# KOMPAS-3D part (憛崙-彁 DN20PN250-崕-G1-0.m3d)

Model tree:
1. Объединить компоненты:1  (labels: СЕНС-ПР DN20PN250-НО-G1-0)

Referenced files in D:\Савин\!СЕНСОР\3D для заказчика\!Новый перечень\СЕНС-ПР\6. СЕНС-ПР-PN250-НО\DN20\: СЕНС-ПР DN20PN250-НО-G1-0.a3d
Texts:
  СЕНС-ПР DN20PN250-НО-G1-0
  ООО НПП Сенсор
